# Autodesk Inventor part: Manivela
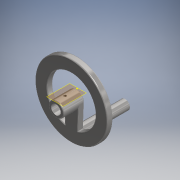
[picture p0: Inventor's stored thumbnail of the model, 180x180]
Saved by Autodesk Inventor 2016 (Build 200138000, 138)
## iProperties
Created: 2016-02
Part Number: Manivela
Material: Stainless Steel
Document SubType Name: Modeling
Designer: Vertex
Density: 8 g/cm^3
Appearance: Semi-Polished
Mass: 759.354 g
Surface Area: 286.814 cm^2
Volume: 94.9192 cm^3
Author: Vertex
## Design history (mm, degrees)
sketch "Sketch1"
  geometry: C1 r 12.5 at (0, 0); 1 further point
  constraints: 1 centre point
  dimensions: "d1" = 25 diameter of C1
extrude "Extrusion1" new body sketch "Sketch1" distance "d2" = 35; taper "d3" = 0 deg
hole "Hole1" diameter "d6" = 16; stored, may be unused: countersink angle "d10" = 90 deg, drill point angle "d12" = 118 deg; dims "d4" = 10, "d5" = 10, "d7" = 7.5, "d8" = 3.75, "d9" = 2.5, "d11" = 30
workplane "Work Plane1"
sketch "Sketch2"
  geometry: L1 (12.5, 35)-(-12.5, 35) reference; C1 r 2.5 at (0, 20); 1 further point
  constraints: 1 centre point
  dimensions: "d14" = 5 diameter of C1; "d15" = 15 distance from line of C1.centre L1
hole "Hole2" sketch "Sketch2" at (0, 20) diameter "d16" = 4.13; stored, may be unused: countersink angle "d20" = 90 deg, drill point angle "d22" = 118 deg; dims "d17" = 10, "d18" = 3.75, "d19" = 2.5, "d21" = 10
sketch "Sketch3"
  geometry: 1 further point
sketch "Sketch4" dims "d29" = 120 (derived)
  geometry: L1 (10.877, -38.493)-(12.489, -0.523); L2 (-10.9, -38.486)-(-12.489, -0.523); A1 r 12.5 centre (0, 0) between (12.489, -0.53) and (-12.489, -0.523); A2 r 40 centre (0, 0) between (10.877, -38.493) and (-10.9, -38.486); 4 further points
  constraints: 5 point on circle, 4 end point, 3 coincident, 2 centre point, 2 vertical alignment, 1 horizontal alignment, 1 point on line, 7 other
  dimensions: "d27" = 60 distance of point (0, 0) point (0, -60); "d30" = 80 diameter of A2; "d31" = 21.77766 distance of L1.start L2.start
extrude "Extrusion2" join sketch "Sketch4" distance "d32" = 10; taper "d33" = 0 deg
fillet "Fillet1" dims "d34" = 2
sketch "Sketch5"
  geometry: C1 r 8 at (0, -50); 1 further point
  constraints: 1 centre point
  dimensions: "d35" = 16 diameter of C1
extrude "Extrusion3" join sketch "Sketch5" distance "d36" = 80; taper "d37" = 0 deg
sketch "Sketch6"
  geometry: C1 r 2.5 at (0, 0); 1 further point
  constraints: 1 centre point
  dimensions: "d38" = 5 diameter of C1
hole "Hole3" sketch "Sketch6" at (0, 0) diameter "d39" = 4.13; stored, may be unused: countersink angle "d43" = 90 deg, drill point angle "d45" = 118 deg; dims "d40" = 10, "d41" = 3.75, "d42" = 2.5, "d44" = 20
body "Solid1"
other parameters: "d13" = 12.5
